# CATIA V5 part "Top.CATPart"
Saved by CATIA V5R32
Part number: Part1.1
Bounding box of the stored display mesh (mm): x -50 to 50, y -25 to 25, z -20 to 10
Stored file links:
  D:\PROJECTS\Project 2022\CATIA V5 6R 2022\Resources\Part Files\c12_catia_v5_6r2022_prt\c12_catia_v5-6r2022 figr_12-22\Top.CATPart
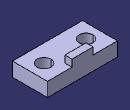
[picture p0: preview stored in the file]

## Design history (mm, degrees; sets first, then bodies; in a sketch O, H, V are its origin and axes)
Body1 (main body)
  Sketch1 on xy-plane, origin (0, 0, 0), H (1, 0, 0), V (0, 1, 0)
    line L1 (50, 25) -> (50, -25)
    line L2 (50, -25) -> (-50, -25)
    line L3 (-50, -25) -> (-50, 25)
    line L4 (-50, 25) -> (50, 25)
    circle A1 centre (-30, 0) radius 10
    point P5 (-30, 0)
    circle A2 centre (30, 0) radius 10
    length L2 = 100
    length L1 = 50
    radius A1 = 10
    distance P5 V = 30
    vertical: L1 V, L3 V
    horizontal: L2 H, L4 H
    equidistance: L1 L3 O, L2 L4 O
    coincidence: P5 H
    symmetry: A1 A2 V
  Pad1: profile Sketch1, direction (0, 0, -1), length 20
  Sketch2 on face of Pad1, origin (0, 0, 0), H (1, 0, 0), V (0, 1, 0)
    line L1 (-15, 25) -> (15, 25)
    line L2 (15, 25) -> (15, 15)
    line L3 (15, 15) -> (-15, 15)
    line L4 (-15, 15) -> (-15, 25)
    reference projected line E1 (50, 25) -> (-50, 25) from edge [face of Pad1 | face of Pad1]
    length L1 = 30
    distance L4 V = 15
    length L2 = 10
    horizontal: L1 H, L3 H
    vertical: L2 V, L4 V
    coincidence: L1 E1
  Pad2: profile Sketch2, direction (0, 0, 1), length 10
